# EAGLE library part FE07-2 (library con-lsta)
FEMALE HEADER
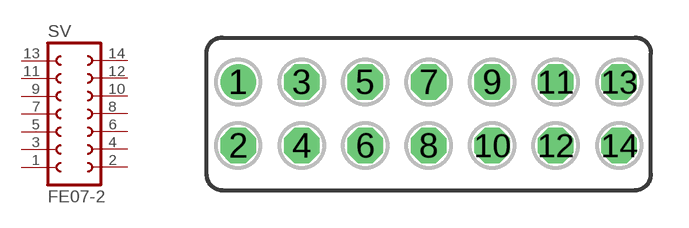
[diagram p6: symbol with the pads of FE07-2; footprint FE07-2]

Designator prefix SV

## FE07-2 (OC_FARNELL: unknown; OC_NEWARK: unknown)  [FE07-2]
1  1  pas
2  2  pas
3  3  pas
4  4  pas
5  5  pas
6  6  pas
7  7  pas
8  8  pas
9  9  pas
10  10  pas
11  11  pas
12  12  pas
13  13  pas
14  14  pas

## Footprint FE07-2 (pad centres in mm)
FEMALE HEADER
drill 0.914 round: 1 -7.62,1.27
drill 0.914 octagon: 2 -7.62,-1.27; 3 -5.08,1.27; 4 -5.08,-1.27; 5 -2.54,1.27; 6 -2.54,-1.27; 7 0,1.27; 8 0,-1.27; 9 2.54,1.27; 10 2.54,-1.27; 11 5.08,1.27; 12 5.08,-1.27; 13 7.62,1.27; 14 7.62,-1.27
